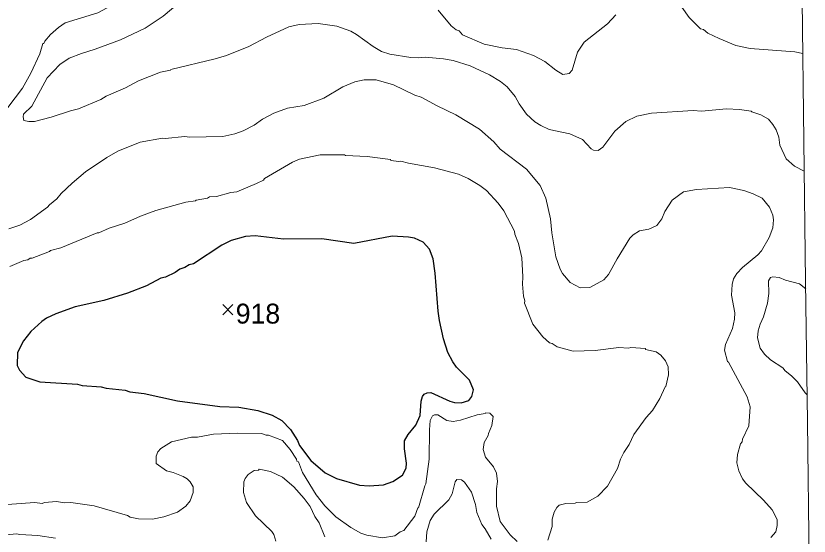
# Model space of a CAD drawing. Extents: x 265.7 to 292.1, y 7676.2 to 7704.2.
# Drawn here: x 288.719 to 291.905, y 7692.446 to 7694.536 of the extents above; entities that cross this region are included whole.
import ezdxf
from ezdxf.enums import TextEntityAlignment as Align

# ---------------------------------------------------------------- set-up
doc = ezdxf.new("R2010")
doc.units = 0
doc.header["$LTSCALE"] = 0.032
for name, color, linetype, lineweight in [('1', 7, 'Continuous', 25), ('2', 7, 'Continuous', 13), ('21', 7, 'Continuous', 25), ('63', 7, 'Continuous', 25)]:
    doc.layers.add(name, color=color, linetype=linetype, lineweight=lineweight)
doc.layers.add('61', color=7, linetype='Continuous')

msp = doc.modelspace()

# ---------------------------------------------------------------- linework, layer by layer
at = {"layer": '1'}
msp.add_lwpolyline([(290.2961, 7693.6477), (290.2299, 7693.6508), (290.0767, 7693.6221), (289.9474, 7693.6405), (289.7942, 7693.6389), (289.6793, 7693.6532), (289.641, 7693.65), (289.5835, 7693.6341), (289.5452, 7693.6149), (289.4319, 7693.5407), (289.4143, 7693.5359), (289.3968, 7693.5248), (289.3776, 7693.5184), (289.3585, 7693.5048), (289.3202, 7693.4865), (289.301, 7693.4825), (289.2436, 7693.4521), (289.167, 7693.4226), (289.0712, 7693.3923), (288.9563, 7693.3676), (288.8797, 7693.3396), (288.8414, 7693.3213), (288.8223, 7693.3085), (288.7792, 7693.2678), (288.7488, 7693.2311), (288.7249, 7693.184), (288.7241, 7693.1314), (288.7329, 7693.1122), (288.7584, 7693.0843), (288.8143, 7693.0659), (288.9659, 7693.0564), (288.985, 7693.0516), (289.0616, 7693.0452), (289.0808, 7693.0404), (289.1574, 7693.0324), (289.1766, 7693.026), (289.234, 7693.0196), (289.3681, 7692.9901), (289.5372, 7692.967), (289.6138, 7692.9638), (289.6904, 7692.951), (289.7479, 7692.9319), (289.7862, 7692.9103), (289.8213, 7692.8744), (289.85, 7692.8297), (289.858, 7692.8106), (289.9035, 7692.75), (289.9609, 7692.6997), (290.0064, 7692.6773), (290.099, 7692.651), (290.1373, 7692.6478), (290.1948, 7692.6526), (290.2331, 7692.6661), (290.2722, 7692.6909), (290.2857, 7692.7196), (290.2881, 7692.7388), (290.2801, 7692.7962), (290.2793, 7692.8282), (290.2937, 7692.8537), (290.3248, 7692.892), (290.3424, 7692.9303), (290.3471, 7692.9877), (290.3519, 7693.0069), (290.3583, 7693.0157), (290.3703, 7693.022), (290.3847, 7693.0236), (290.4613, 7692.9877), (290.4804, 7692.9829), (290.5076, 7692.9813), (290.5379, 7692.9909), (290.5506, 7693.0069), (290.557, 7693.034), (290.5402, 7693.0731), (290.4884, 7693.1242), (290.4732, 7693.1457), (290.4541, 7693.184), (290.4365, 7693.2383), (290.4198, 7693.3117), (290.4142, 7693.35), (290.4022, 7693.5032), (290.3942, 7693.5607), (290.3799, 7693.599), (290.3551, 7693.6269), (290.3192, 7693.6437)], close=True, dxfattribs=at)
at = {"layer": '2'}
for points in [[(288.6866, 7694.1679), (288.7456, 7694.2453), (288.7792, 7694.306), (288.8143, 7694.3842), (288.827, 7694.4249), (288.8302, 7694.4249), (288.835, 7694.4352), (288.8574, 7694.4616), (288.8893, 7694.4895), (288.9164, 7694.5079), (289.0473, 7694.5485), (289.0999, 7694.5765), (289.1518, 7694.6204), (289.1654, 7694.6387)], [(289.3697, 7694.5845), (289.3106, 7694.535), (289.238, 7694.4863), (289.1383, 7694.44), (289.0377, 7694.4025), (288.9818, 7694.3858), (288.9324, 7694.3658), (288.8957, 7694.3403), (288.8446, 7694.2868), (288.7824, 7694.1735), (288.7496, 7694.1408), (288.7472, 7694.1304), (288.7504, 7694.1161), (288.7712, 7694.1113), (288.7935, 7694.1121), (288.8606, 7694.1288), (288.938, 7694.1552), (288.9707, 7694.1623), (289.06, 7694.2006), (289.0808, 7694.2134), (289.159, 7694.2477), (289.2117, 7694.2756), (289.2994, 7694.31), (289.3393, 7694.3179), (289.3409, 7694.3211), (289.5197, 7694.3634), (289.5644, 7694.377), (289.6537, 7694.4129), (289.7247, 7694.4504), (289.8149, 7694.4919), (289.8564, 7694.5015), (289.933, 7694.5063), (290.008, 7694.4951), (290.0639, 7694.4743), (290.0862, 7694.4616), (290.1533, 7694.4129), (290.1868, 7694.3937), (290.2203, 7694.3826), (290.3049, 7694.369), (290.3352, 7694.3674), (290.3623, 7694.3706), (290.4357, 7694.3642), (290.4756, 7694.357), (290.5427, 7694.3355), (290.6209, 7694.2988), (290.6655, 7694.2725), (290.6919, 7694.2509), (290.7246, 7694.2118), (290.7397, 7694.1823), (290.7701, 7694.1416), (290.8036, 7694.1105), (290.8267, 7694.0953), (290.8603, 7694.0801), (290.9432, 7694.0626), (290.9943, 7694.0394), (291.0294, 7694.0027), (291.039, 7693.9972), (291.0581, 7693.9956), (291.0757, 7694.0083), (291.1244, 7694.073), (291.1683, 7694.1113), (291.213, 7694.1328), (291.272, 7694.1456), (291.4396, 7694.156), (291.4731, 7694.1536), (291.5736, 7694.1631), (291.6247, 7694.1607), (291.6726, 7694.1536), (291.675, 7694.1504), (291.7109, 7694.1384), (291.7412, 7694.1208), (291.7587, 7694.1001), (291.7723, 7694.0778), (291.7827, 7694.049), (291.7867, 7694.0171), (291.8122, 7693.9613), (291.8465, 7693.9325), (291.8853, 7693.912)], [(290.415, 7694.5597), (290.4668, 7694.4967), (290.4868, 7694.4807), (290.4988, 7694.4759), (290.5131, 7694.46), (290.6001, 7694.4225), (290.6719, 7694.4073), (290.7294, 7694.4009), (290.798, 7694.377), (290.8427, 7694.353), (290.8874, 7694.3187), (290.9161, 7694.3012), (290.9416, 7694.3052), (290.9536, 7694.3179), (290.9751, 7694.3906), (291.0007, 7694.4305), (291.0956, 7694.5039), (291.1284, 7694.5406)], [(291.3933, 7694.5709), (291.4236, 7694.5294), (291.4683, 7694.4839), (291.4803, 7694.4815)], [(291.4803, 7694.4815), (291.4986, 7694.4672), (291.5433, 7694.4448), (291.6103, 7694.4177), (291.6678, 7694.4049), (291.8481, 7694.3914), (291.8794, 7694.3848)], [(290.8714, 7693.6644), (290.8666, 7693.7203), (290.8467, 7693.8033), (290.8243, 7693.8543), (290.7701, 7693.9206), (290.6639, 7694.0003), (290.6384, 7694.0299), (290.581, 7694.0817), (290.486, 7694.1384), (290.4102, 7694.1743), (290.3464, 7694.2094), (290.3208, 7694.2182), (290.2354, 7694.2597), (290.166, 7694.2796), (290.1181, 7694.2796), (290.0798, 7694.2717), (290.032, 7694.2517), (289.9554, 7694.2054), (289.8772, 7694.1767), (289.8101, 7694.1655), (289.7543, 7694.1456), (289.7096, 7694.1208), (289.6761, 7694.0969), (289.6314, 7694.0746), (289.5979, 7694.0618), (289.55, 7694.0522), (289.4159, 7694.049), (289.3968, 7694.0522), (289.3186, 7694.0434), (289.3074, 7694.045), (289.218, 7694.0291), (289.1287, 7693.9932), (289.084, 7693.9676), (288.9986, 7693.9094), (288.9443, 7693.8647), (288.9005, 7693.8224), (288.8829, 7693.8009), (288.8534, 7693.7777), (288.8462, 7693.7681), (288.7776, 7693.7179), (288.7345, 7693.6955), (288.6898, 7693.6812)], [(289.6059, 7693.8296), (289.6857, 7693.8623), (289.7136, 7693.8767), (289.7176, 7693.8831), (289.8293, 7693.9485), (289.858, 7693.9605), (289.941, 7693.978)], [(289.941, 7693.978), (290.0391, 7693.978), (290.0431, 7693.9748), (290.1293, 7693.9708), (290.2235, 7693.9589), (290.2251, 7693.9557), (290.257, 7693.9509), (290.265, 7693.9525), (290.2953, 7693.9445), (290.4006, 7693.9261), (290.4964, 7693.8998), (290.5347, 7693.883), (290.5826, 7693.8551), (290.6089, 7693.8344), (290.656, 7693.7841), (290.6791, 7693.753), (290.7214, 7693.6716), (290.723, 7693.6596), (290.7374, 7693.6213), (290.7509, 7693.5639), (290.7549, 7693.4873), (290.7533, 7693.4585), (290.7581, 7693.4107), (290.7629, 7693.3915), (290.7613, 7693.3819), (290.7948, 7693.2974), (290.8347, 7693.2463), (290.8626, 7693.2231), (290.873, 7693.2199), (290.8922, 7693.2064), (290.9576, 7693.1896), (291.0454, 7693.1912), (291.1411, 7693.2032), (291.1794, 7693.2016), (291.189, 7693.204), (291.2473, 7693.1992), (291.2481, 7693.196), (291.2904, 7693.1864), (291.3087, 7693.1737), (291.3278, 7693.1505), (291.339, 7693.1266), (291.3398, 7693.0947), (291.3294, 7693.0468), (291.3263, 7693.0452), (291.3055, 7692.9989), (291.2752, 7692.951), (291.2504, 7692.9231), (291.201, 7692.8537), (291.1826, 7692.8138), (291.1603, 7692.7819), (291.1467, 7692.7547), (291.1355, 7692.718), (291.0948, 7692.6462), (291.0557, 7692.6063), (291.0135, 7692.5824), (290.9704, 7692.5816), (290.9656, 7692.5784), (290.9273, 7692.5768), (290.9009, 7692.5704), (290.8914, 7692.5608), (290.881, 7692.5425), (290.873, 7692.5138), (290.8722, 7692.485), (290.8547, 7692.4292)], [(288.6938, 7693.5296), (288.7504, 7693.5535), (288.7664, 7693.5567), (288.776, 7693.5631), (288.784, 7693.5631), (288.8542, 7693.5894), (288.8582, 7693.5942), (288.8989, 7693.6038), (289.0449, 7693.6644), (289.0521, 7693.6644), (289.0936, 7693.6828), (289.1558, 7693.7035), (289.2196, 7693.7322), (289.2803, 7693.7546), (289.4016, 7693.7881), (289.4399, 7693.7929), (289.4431, 7693.7961), (289.4878, 7693.8041), (289.4965, 7693.8088), (289.5245, 7693.8104), (289.5819, 7693.8264), (289.6059, 7693.8296)], [(291.7508, 7692.4403), (291.7715, 7692.4635), (291.7771, 7692.4882), (291.7763, 7692.513), (291.7564, 7692.5521), (291.7212, 7692.5904), (291.6502, 7692.659), (291.6375, 7692.6765), (291.6223, 7692.7085), (291.6143, 7692.7404), (291.6167, 7692.7739), (291.6287, 7692.8162), (291.6359, 7692.8242), (291.6375, 7692.8353), (291.663, 7692.8896), (291.6686, 7692.9654), (291.6566, 7693.0053), (291.5808, 7693.1449), (291.5768, 7693.1473), (291.5656, 7693.1936), (291.5696, 7693.216), (291.5968, 7693.2798), (291.6055, 7693.3181), (291.6063, 7693.3436), (291.5936, 7693.4139), (291.596, 7693.4569), (291.6008, 7693.4793), (291.6143, 7693.5008), (291.6375, 7693.5256), (291.6989, 7693.5766), (291.7133, 7693.5926), (291.7444, 7693.6461), (291.7587, 7693.6852), (291.7619, 7693.7163), (291.7587, 7693.7362), (291.746, 7693.7681), (291.7165, 7693.8033), (291.6806, 7693.8216), (291.6423, 7693.8344), (291.5848, 7693.8471), (291.4523, 7693.8392), (291.3997, 7693.8288), (291.355, 7693.7961), (291.3247, 7693.7498), (291.3135, 7693.7203), (291.2927, 7693.6939), (291.2616, 7693.6796), (291.2241, 7693.6724), (291.1986, 7693.6572), (291.1842, 7693.6429), (291.1332, 7693.5599), (291.0988, 7693.4968), (291.0797, 7693.4753), (291.0246, 7693.445)], [(291.0246, 7693.445), (290.9847, 7693.4434), (290.9448, 7693.4649), (290.9137, 7693.5016), (290.9049, 7693.5184), (290.8874, 7693.5687), (290.8714, 7693.6644)], [(291.8912, 7693.4395), (291.8657, 7693.4593), (291.8098, 7693.4745), (291.7843, 7693.4857), (291.7588, 7693.4873), (291.75, 7693.4849), (291.7412, 7693.4713), (291.7428, 7693.4202), (291.738, 7693.3819), (291.722, 7693.3277), (291.7077, 7693.2981), (291.7005, 7693.2702), (291.6981, 7693.2423), (291.7085, 7693.2016), (291.7252, 7693.1777), (291.75, 7693.1545), (291.7987, 7693.1226), (291.8082, 7693.1106), (291.8346, 7693.0899), (291.8577, 7693.0659), (291.8888, 7693.0221), (291.8965, 7693.0135)], [(290.7318, 7692.4244), (290.7046, 7692.4507), (290.6639, 7692.505), (290.6488, 7692.5664), (290.6496, 7692.6366), (290.6536, 7692.6654), (290.6496, 7692.6989), (290.6368, 7692.7244), (290.6049, 7692.7635), (290.5953, 7692.7946), (290.6001, 7692.8218), (290.6161, 7692.8497), (290.6169, 7692.8585), (290.6304, 7692.8904), (290.6352, 7692.9263), (290.6225, 7692.9399), (290.6049, 7692.9415), (290.6041, 7692.9391), (290.5714, 7692.9327), (290.5044, 7692.9119), (290.4756, 7692.9063), (290.4493, 7692.9103), (290.4134, 7692.9327), (290.4006, 7692.9335), (290.3926, 7692.9287), (290.3831, 7692.9111), (290.3799, 7692.8728)], [(290.3799, 7692.8728), (290.3791, 7692.7547), (290.3655, 7692.6558), (290.3607, 7692.6478), (290.336, 7692.56), (290.3336, 7692.56), (290.3208, 7692.5265)], [(290.3208, 7692.5265), (290.2769, 7692.4683), (290.2618, 7692.4627), (290.2402, 7692.4475), (290.1916, 7692.4387), (290.1277, 7692.4499), (290.1038, 7692.4579), (290.0639, 7692.481), (290.0032, 7692.5233), (289.9601, 7692.568), (289.9242, 7692.6119), (289.87, 7692.7021), (289.8532, 7692.7444), (289.8476, 7692.7468), (289.846, 7692.7555), (289.8197, 7692.7946), (289.7894, 7692.8297), (289.7335, 7692.8513), (289.724, 7692.8513), (289.7048, 7692.8577), (289.609, 7692.8601), (289.5117, 7692.8553), (289.4479, 7692.8433), (289.4239, 7692.8433), (289.3441, 7692.825), (289.301, 7692.7986), (289.2883, 7692.7851), (289.2827, 7692.7675), (289.2819, 7692.7372), (289.3234, 7692.7084), (289.3505, 7692.7021), (289.3904, 7692.6861), (289.4064, 7692.6765), (289.4183, 7692.6646), (289.4311, 7692.6438), (289.4311, 7692.6207), (289.4191, 7692.5872), (289.4008, 7692.5664), (289.3681, 7692.5425), (289.3122, 7692.5241), (289.2675, 7692.5145), (289.2117, 7692.5161), (289.1781, 7692.5225), (289.167, 7692.5289), (289.0329, 7692.5672), (288.9388, 7692.5816), (288.914, 7692.58), (288.8813, 7692.5848), (288.8334, 7692.5816), (288.8239, 7692.5776), (288.7951, 7692.5808), (288.5541, 7692.564)], [(289.763, 7692.426), (289.7551, 7692.4523), (289.7471, 7692.4643), (289.6817, 7692.5281), (289.6449, 7692.5808), (289.633, 7692.6207), (289.6338, 7692.6646), (289.6394, 7692.6781), (289.6513, 7692.6933), (289.6761, 7692.71), (289.6936, 7692.7116), (289.6952, 7692.7148), (289.7415, 7692.7053), (289.7894, 7692.6829), (289.8349, 7692.6438), (289.8764, 7692.5975), (289.9003, 7692.5648), (289.9194, 7692.5249), (289.9362, 7692.4994), (289.9593, 7692.4435)], [(290.3671, 7692.4228), (290.3695, 7692.4627), (290.3823, 7692.509), (290.3982, 7692.5345), (290.4581, 7692.592), (290.4716, 7692.6159), (290.4836, 7692.6638), (290.4892, 7692.6741), (290.5091, 7692.6725)], [(290.5091, 7692.6725), (290.5203, 7692.663), (290.5482, 7692.6231), (290.565, 7692.5728), (290.5706, 7692.5409), (290.5905, 7692.493), (290.6041, 7692.4755)], [(288.3515, 7692.4268), (288.4089, 7692.4595), (288.4456, 7692.4683), (288.5254, 7692.4683), (288.6148, 7692.4619), (288.6467, 7692.4555), (288.6946, 7692.4523), (288.7217, 7692.4555), (288.7345, 7692.4523), (288.8063, 7692.4491), (288.8781, 7692.4379)], [(290.6041, 7692.4755), (290.628, 7692.434)]]:
    msp.add_lwpolyline(points, dxfattribs=at)
at = {"layer": '21'}
for p, q in [((289.5494, 7693.3767), (289.5906, 7693.3355)), ((289.5906, 7693.3767), (289.5494, 7693.3355))]:
    msp.add_line(p, q, dxfattribs=at)
at = {"layer": '63', "lineweight": 13}
msp.add_lwpolyline([(291.7577, 7704.203), (291.7647, 7703.638), (291.7717, 7703.0731), (291.7787, 7702.5082), (291.7857, 7701.9433), (291.7927, 7701.3784), (291.7997, 7700.8135), (291.8067, 7700.2486), (291.8137, 7699.6837), (291.8207, 7699.1188), (291.8277, 7698.5539), (291.8347, 7697.9889), (291.8417, 7697.424), (291.8487, 7696.8591), (291.8557, 7696.2942), (291.8628, 7695.7293), (291.8698, 7695.1644), (291.8768, 7694.5995), (291.8838, 7694.0345), (291.8908, 7693.4696), (291.8978, 7692.9047), (291.9049, 7692.3398)], dxfattribs=at)

# ---------------------------------------------------------------- texts
at = {"layer": '61'}
msp.add_text('918', height=0.08, dxfattribs=at).set_placement((289.6909, 7693.3), align=Align.CENTER)

doc.saveas('drawing.dxf')
